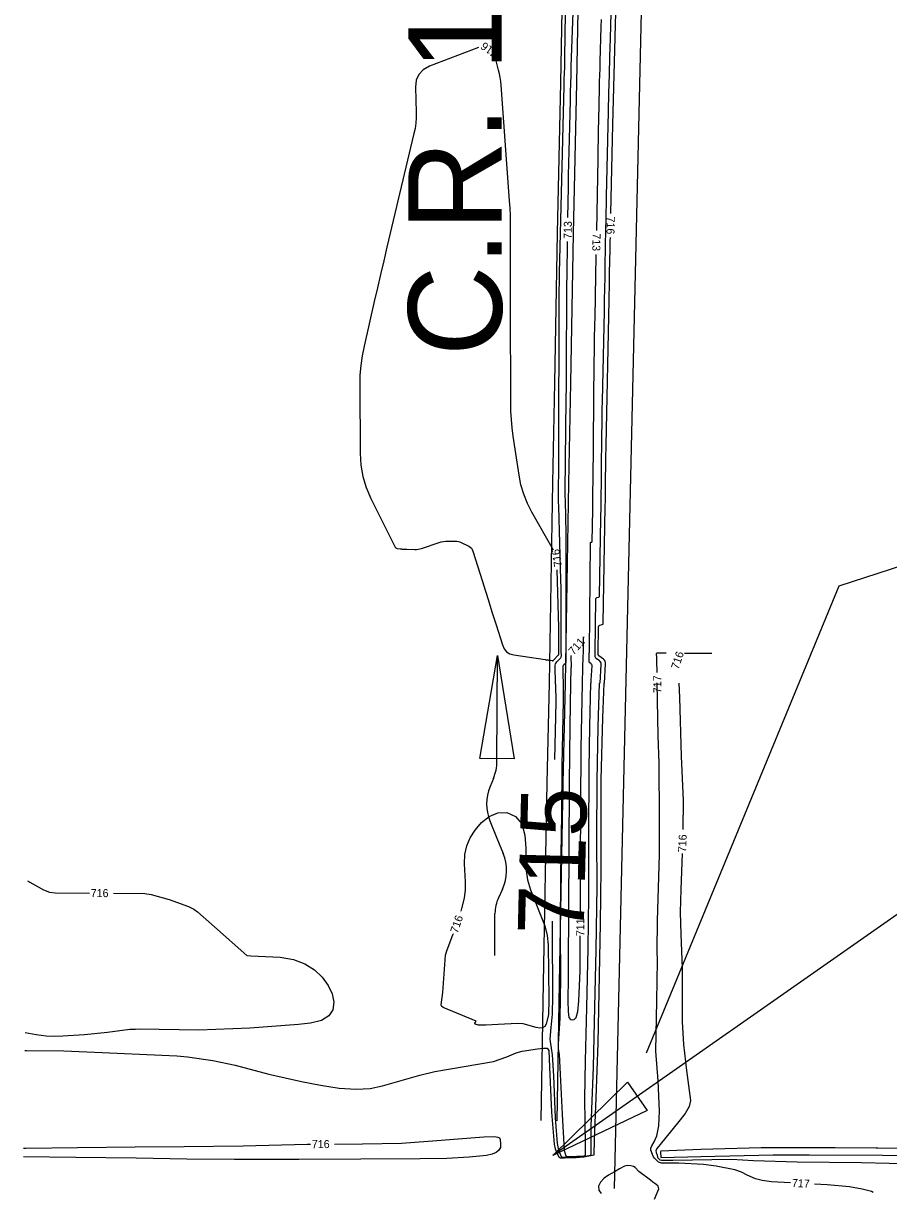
# Model space of a CAD drawing. Extents: x -468563856 to 36492962, y -306094093 to 11899197.
# Drawn here: x 1818863 to 1819296, y 531006 to 531590 of the extents above; entities that cross this region are included whole.
import ezdxf

# ---------------------------------------------------------------- set-up
doc = ezdxf.new("R2010")
doc.units = 0
for name, color, linetype in [('DT_X_Contour_Minor', 7, 'Continuous'), ('DT_X_Terrain_Boundary', 7, 'Continuous'), ('Level 19', 7, 'Continuous'), ('Level 31', 7, 'Continuous'), ('Level 40', 7, 'Continuous'), ('Level 56', 7, 'Continuous')]:
    doc.layers.add(name, color=color, linetype=linetype)

msp = doc.modelspace()

# ---------------------------------------------------------------- linework, layer by layer
at = {"layer": 'DT_X_Contour_Minor'}
for points in [[(1819157.17, 531495.03), (1819158.17, 531539.46), (1819158.46, 531551.92), (1819158.77, 531564.38), (1819159.09, 531576.84), (1819159.44, 531589.3), (1819161.01, 531644.73), (1819161.09, 531647.34), (1819161.18, 531649.96), (1819161.27, 531652.58), (1819161.37, 531655.2), (1819161.72, 531663.74), (1819161.79, 531665.58), (1819161.86, 531667.41), (1819161.92, 531669.24), (1819161.98, 531671.07), (1819164.36, 531744.92)], [(1819129.49, 531260), (1819129.26, 531268.51), (1819129.3, 531269.17), (1819129.47, 531269.79), (1819129.76, 531270.35), (1819130.17, 531270.87), (1819131.96, 531272.75), (1819132.14, 531272.98), (1819132.27, 531273.22), (1819132.34, 531273.49), (1819132.37, 531273.78), (1819132.37, 531274.75), (1819132.36, 531274.96), (1819132.36, 531275.17), (1819132.36, 531275.37), (1819132.36, 531275.58), (1819132.34, 531295.09), (1819132.32, 531299.27), (1819132.28, 531303.45), (1819132.2, 531307.63), (1819132.1, 531311.81), (1819131.05, 531348.48), (1819130.99, 531350.89), (1819130.96, 531353.3), (1819130.95, 531355.71), (1819130.96, 531358.12), (1819131.04, 531365.99), (1819131.06, 531367.67), (1819131.07, 531369.36), (1819131.08, 531371.04), (1819131.09, 531372.73), (1819131.34, 531454.17), (1819131.34, 531455.91), (1819131.36, 531457.64), (1819131.38, 531459.37), (1819131.4, 531461.1), (1819131.49, 531466.76), (1819131.51, 531467.98), (1819131.54, 531469.19), (1819131.56, 531470.4), (1819131.59, 531471.62), (1819133.73, 531558.76), (1819133.77, 531560.17), (1819133.81, 531561.58), (1819133.85, 531562.99), (1819133.89, 531564.4), (1819134.04, 531569), (1819134.07, 531569.99), (1819134.1, 531570.97), (1819134.12, 531571.96), (1819134.14, 531572.95), (1819134.86, 531617.56)], [(1819151.72, 531260.14), (1819152.25, 531269.51), (1819152.22, 531270.06), (1819152.07, 531270.54), (1819151.79, 531270.97), (1819151.4, 531271.34), (1819149.83, 531272.53), (1819149.59, 531272.76), (1819149.42, 531273.01), (1819149.33, 531273.3), (1819149.31, 531273.62), (1819149.34, 531274.73), (1819149.35, 531274.97), (1819149.35, 531275.21), (1819149.36, 531275.44), (1819149.36, 531275.68), (1819149.63, 531302.24), (1819149.67, 531302.51), (1819149.77, 531302.72), (1819149.95, 531302.88), (1819150.19, 531302.99), (1819151.1, 531303.26), (1819151.27, 531303.33), (1819151.39, 531303.44), (1819151.47, 531303.59), (1819151.49, 531303.78), (1819152.17, 531342.63), (1819152.27, 531348.44), (1819152.35, 531354.26), (1819152.43, 531360.08), (1819152.49, 531365.9), (1819152.69, 531384.9), (1819152.74, 531388.97), (1819152.79, 531393.05), (1819152.86, 531397.12), (1819152.94, 531401.19), (1819153.88, 531446.12), (1819154, 531451.81), (1819154.11, 531457.51), (1819154.22, 531463.2), (1819154.32, 531468.89), (1819154.67, 531487.49), (1819154.74, 531491.47), (1819154.82, 531495.46), (1819154.9, 531499.44), (1819154.99, 531503.43), (1819155.95, 531546.05), (1819156.16, 531555.19), (1819156.38, 531564.32), (1819156.62, 531573.45), (1819156.88, 531582.58), (1819157.97, 531621.19)], [(1819135.67, 531492.95), (1819135.92, 531508.2), (1819136.02, 531514.18), (1819136.13, 531520.16), (1819136.26, 531526.15), (1819136.4, 531532.13), (1819136.88, 531551.68), (1819136.99, 531555.86), (1819137.1, 531560.05), (1819137.23, 531564.24), (1819137.36, 531568.43), (1819138.54, 531604.73)], [(1819150.06, 531486.44), (1819150.72, 531522.35), (1819150.81, 531527.18), (1819150.9, 531532.01), (1819151, 531536.84), (1819151.11, 531541.67), (1819151.46, 531557.44), (1819151.54, 531560.82), (1819151.62, 531564.2), (1819151.71, 531567.58), (1819151.81, 531570.96), (1819152.3, 531588.34), (1819152.41, 531592.07)], [(1819090.94, 531578.05), (1819066.45, 531568.59), (1819063.32, 531566.89), (1819061.11, 531564.58), (1819059.82, 531561.66), (1819059.46, 531558.13), (1819059.75, 531545.57), (1819059.73, 531542.89), (1819059.54, 531540.23), (1819059.17, 531537.58), (1819058.64, 531534.96), (1819045.12, 531478.22), (1819043.51, 531471.41), (1819041.91, 531464.59), (1819040.33, 531457.77), (1819038.76, 531450.95), (1819033.66, 531428.65), (1819032.71, 531423.86), (1819032.03, 531419.04), (1819031.63, 531414.18), (1819031.51, 531409.3)], [(1819128.46, 531326.75), (1819117.68, 531345.6), (1819115.4, 531350.03), (1819113.56, 531354.62), (1819112.17, 531359.37), (1819111.21, 531364.26), (1819108.34, 531383.65), (1819107.8, 531387.81), (1819107.41, 531391.98), (1819107.16, 531396.16), (1819107.07, 531400.35), (1819106.87, 531448.67), (1819106.85, 531453.9), (1819106.85, 531459.13), (1819106.86, 531464.36), (1819106.88, 531469.59), (1819106.97, 531486.68), (1819106.95, 531490.35), (1819106.86, 531494), (1819106.7, 531497.66), (1819106.47, 531501.32), (1819102.27, 531559.1), (1819102.08, 531561.03), (1819101.8, 531562.94), (1819101.43, 531564.83), (1819100.96, 531566.71), (1819099.53, 531571.93)], [(1819153.97, 531260.16), (1819154.51, 531269.84), (1819154.47, 531270.52), (1819154.28, 531271.12), (1819153.95, 531271.66), (1819153.46, 531272.12), (1819151.08, 531273.92), (1819150.96, 531274.03), (1819150.88, 531274.16), (1819150.83, 531274.3), (1819150.82, 531274.46), (1819150.84, 531275.01), (1819150.84, 531275.13), (1819150.85, 531275.25), (1819150.85, 531275.36), (1819150.85, 531275.48), (1819150.98, 531288.21), (1819151.03, 531288.55), (1819151.16, 531288.82), (1819151.38, 531289.02), (1819151.69, 531289.16), (1819152.85, 531289.51), (1819153.07, 531289.6), (1819153.23, 531289.75), (1819153.32, 531289.94), (1819153.36, 531290.17), (1819154.37, 531348.5), (1819154.42, 531351.53), (1819154.47, 531354.56), (1819154.51, 531357.59), (1819154.54, 531360.62), (1819154.64, 531370.52), (1819154.67, 531372.65), (1819154.7, 531374.77), (1819154.73, 531376.89), (1819154.78, 531379.01), (1819156.29, 531451.72), (1819156.35, 531454.66), (1819156.41, 531457.6), (1819156.47, 531460.53), (1819156.52, 531463.47), (1819156.7, 531473.07), (1819156.74, 531475.13), (1819156.78, 531477.18), (1819156.82, 531479.24), (1819156.87, 531481.3), (1819156.9, 531483.03)], [(1819133.4, 531260.03), (1819133.4, 531260.31), (1819133.39, 531261.6), (1819133.36, 531262.9), (1819133.22, 531268.25), (1819133.24, 531268.58), (1819133.32, 531268.89), (1819133.47, 531269.18), (1819133.68, 531269.44), (1819134.45, 531270.25), (1819134.6, 531270.43), (1819134.7, 531270.63), (1819134.76, 531270.85), (1819134.78, 531271.08), (1819134.77, 531273.94), (1819134.77, 531274.55), (1819134.77, 531275.16), (1819134.77, 531275.78), (1819134.77, 531276.39), (1819134.71, 531336.26), (1819134.7, 531338.24), (1819134.67, 531340.21), (1819134.64, 531342.19), (1819134.59, 531344.16), (1819134.4, 531350.61), (1819134.37, 531352), (1819134.35, 531353.38), (1819134.35, 531354.76), (1819134.35, 531356.14), (1819134.82, 531402.33), (1819134.88, 531408.43), (1819134.93, 531414.53), (1819134.96, 531420.63), (1819134.98, 531426.73), (1819135.05, 531446.66), (1819135.07, 531450.93), (1819135.1, 531455.2), (1819135.15, 531459.47), (1819135.21, 531463.74), (1819135.48, 531480.95)], [(1819147.24, 531260.11), (1819147.24, 531260.21), (1819147.33, 531261.83), (1819147.72, 531268.86), (1819147.71, 531269.13), (1819147.63, 531269.37), (1819147.49, 531269.59), (1819147.29, 531269.78), (1819146.55, 531270.34), (1819146.41, 531270.47), (1819146.31, 531270.62), (1819146.26, 531270.79), (1819146.24, 531270.99), (1819146.33, 531273.88), (1819146.35, 531274.5), (1819146.37, 531275.12), (1819146.38, 531275.75), (1819146.38, 531276.37), (1819146.93, 531330.3), (1819146.95, 531330.42), (1819146.99, 531330.52), (1819147.07, 531330.59), (1819147.18, 531330.64), (1819147.59, 531330.76), (1819147.66, 531330.79), (1819147.72, 531330.84), (1819147.75, 531330.91), (1819147.77, 531330.99), (1819148.04, 531346.86), (1819148.1, 531350.26), (1819148.15, 531353.66), (1819148.19, 531357.06), (1819148.23, 531360.46), (1819148.86, 531421.28), (1819148.91, 531425.44), (1819148.96, 531429.6), (1819149.03, 531433.76), (1819149.12, 531437.92), (1819149.4, 531451.51), (1819149.46, 531454.42), (1819149.52, 531457.33), (1819149.57, 531460.24), (1819149.63, 531463.16), (1819149.84, 531474.45)], [(1819031.51, 531409.3), (1819031.65, 531375.1), (1819032, 531369.22), (1819033.01, 531363.5), (1819034.68, 531357.93), (1819037.01, 531352.52), (1819049, 531328.46), (1819049.23, 531328.1), (1819049.53, 531327.82), (1819049.89, 531327.63), (1819050.31, 531327.53), (1819051.79, 531327.35), (1819052.11, 531327.31), (1819052.43, 531327.28), (1819052.75, 531327.26), (1819053.07, 531327.24), (1819054.12, 531327.2), (1819054.34, 531327.19), (1819054.57, 531327.19), (1819054.8, 531327.18), (1819055.02, 531327.17), (1819059.08, 531327.01), (1819059.94, 531327.02), (1819060.79, 531327.11), (1819061.63, 531327.27), (1819062.46, 531327.51), (1819071.24, 531330.52), (1819072.32, 531330.85), (1819073.41, 531331.07), (1819074.51, 531331.21), (1819075.63, 531331.26), (1819079.32, 531331.26), (1819080.1, 531331.21), (1819080.85, 531331.08), (1819081.59, 531330.86), (1819082.31, 531330.55), (1819086.03, 531328.71), (1819086.76, 531328.26), (1819087.35, 531327.69), (1819087.82, 531327.01), (1819088.15, 531326.22), (1819092.89, 531311.08), (1819093.56, 531308.92), (1819094.24, 531306.76), (1819094.92, 531304.6), (1819095.59, 531302.44), (1819097.8, 531295.38), (1819098.27, 531293.86), (1819098.75, 531292.35), (1819099.22, 531290.84), (1819099.7, 531289.33), (1819102.85, 531279.31), (1819103.72, 531277.39), (1819104.98, 531275.93), (1819106.62, 531274.91), (1819108.65, 531274.35), (1819124.27, 531271.99), (1819124.69, 531271.93), (1819125.11, 531271.86), (1819125.53, 531271.8), (1819125.94, 531271.74), (1819127.8, 531271.46), (1819127.85, 531271.45), (1819127.9, 531271.44), (1819127.95, 531271.43), (1819128, 531271.43), (1819128.16, 531271.4), (1819128.19, 531271.4), (1819128.22, 531271.41), (1819128.25, 531271.42), (1819128.27, 531271.44), (1819131.02, 531274.32), (1819131.08, 531274.4), (1819131.13, 531274.49), (1819131.15, 531274.58), (1819131.16, 531274.68), (1819131.16, 531275.02), (1819131.16, 531275.09), (1819131.16, 531275.17), (1819131.16, 531275.24), (1819131.16, 531275.31), (1819131.15, 531282.14), (1819131.15, 531283.61), (1819131.13, 531285.07), (1819131.1, 531286.53), (1819131.07, 531287.99), (1819130.25, 531316.77)], [(1819143.01, 531260.09), (1819143.18, 531268), (1819143.19, 531268.02), (1819143.19, 531268.05), (1819143.19, 531268.07), (1819143.19, 531268.09), (1819143.19, 531268.2), (1819143.19, 531268.2), (1819143.19, 531268.21), (1819143.19, 531268.21), (1819143.19, 531268.21), (1819143.18, 531268.22), (1819143.18, 531268.22), (1819143.17, 531268.22), (1819143.17, 531268.23), (1819143.17, 531268.23), (1819143.32, 531273), (1819143.35, 531274.02), (1819143.38, 531275.04), (1819143.4, 531276.07), (1819143.41, 531277.09), (1819143.46, 531282.43), (1819143.46, 531283.15), (1819143.44, 531283.39), (1819143.4, 531283.15), (1819143.34, 531282.43), (1819143.23, 531280.88)], [(1819137.18, 531274.02), (1819137.2, 531268.03), (1819137.2, 531268.02), (1819137.2, 531268.02), (1819137.2, 531268.02), (1819137.19, 531268.01), (1819137.18, 531268), (1819137.18, 531268), (1819137.18, 531268), (1819137.18, 531267.99), (1819137.18, 531267.99), (1819137.18, 531267.91), (1819137.18, 531267.89), (1819137.18, 531267.88), (1819137.18, 531267.86), (1819137.18, 531267.84), (1819137.03, 531260.05)], [(1819180.29, 531265.54), (1819180.18, 531271.36), (1819180.17, 531271.82), (1819180.15, 531272.27), (1819180.12, 531272.73), (1819180.09, 531273.19), (1819179.96, 531274.68), (1819179.98, 531274.96), (1819180.08, 531275.15), (1819180.28, 531275.27), (1819180.55, 531275.31), (1819182.71, 531275.31), (1819182.95, 531275.31), (1819183.19, 531275.31), (1819183.43, 531275.31), (1819183.67, 531275.32), (1819184.8, 531275.33)], [(1819194.06, 531275.15), (1819206.72, 531275.14), (1819206.82, 531275.14), (1819206.93, 531275.14), (1819207.03, 531275.14), (1819207.14, 531275.14), (1819207.62, 531275.14)], [(1819246.98, 531010.39), (1819237.57, 531010.89), (1819232.84, 531011.48), (1819229.42, 531012.31), (1819225.31, 531014.23), (1819222.55, 531015.72), (1819219.15, 531016.84), (1819209.9, 531018.76), (1819203.53, 531019.55), (1819190.9, 531020.16), (1819182.53, 531020.26), (1819181.01, 531020.74), (1819178.9, 531022.64), (1819178.48, 531023.41), (1819178.02, 531024.48), (1819177.06, 531026.68), (1819177.08, 531027.63), (1819177.61, 531028.92), (1819178.77, 531030.81), (1819180.14, 531033.91), (1819181.18, 531038.93), (1819181.5, 531046.17), (1819180.82, 531061.38), (1819179.63, 531076.19), (1819180.11, 531101.3), (1819180.42, 531121.42), (1819180.29, 531126.46), (1819180.49, 531141.28), (1819181.4, 531174.31), (1819181.48, 531192.4), (1819181.23, 531220.22), (1819180.87, 531233.86), (1819180.35, 531260.37)], [(1818864.04, 531076.5), (1818864.77, 531076.52), (1818883.56, 531076.41), (1818902.71, 531075.57), (1818932.49, 531074.12), (1818940.08, 531073.83), (1818945.34, 531073.38), (1818957.99, 531071.57), (1818969.24, 531069.19), (1818986.01, 531064.73), (1819002.41, 531061), (1819011.8, 531059.17), (1819021.18, 531057.74), (1819029.7, 531057.11), (1819036.78, 531057.53), (1819042.87, 531058.78), (1819061.52, 531064.23), (1819069.08, 531065.94), (1819098.47, 531071.1), (1819105.08, 531073.39), (1819109.81, 531075.37), (1819112.74, 531076.19), (1819120.36, 531077.41), (1819123.52, 531077.71), (1819125.32, 531077.63), (1819126.06, 531076.49), (1819126.52, 531068.18), (1819127.45, 531045.77), (1819128.79, 531029.62), (1819129.34, 531027.38), (1819130.44, 531024.55), (1819131.15, 531023.37), (1819131.9, 531022.82), (1819133.12, 531022.86), (1819133.91, 531022.93), (1819139.86, 531023.05), (1819143.63, 531023.3), (1819148.72, 531024.32), (1819149, 531031.83), (1819149.86, 531052.92), (1819150.71, 531080.12), (1819151.44, 531114.19), (1819151.99, 531139.95), (1819152.3, 531167.43), (1819152.23, 531194.82), (1819152.34, 531211.83), (1819153.08, 531242.86), (1819153.71, 531260.16)], [(1819127.77, 531141.24), (1819127.8, 531135.83), (1819128, 531103.67), (1819127.83, 531094.71), (1819127.12, 531087.94), (1819126.53, 531082.22), (1819127.2, 531077.65), (1819127.71, 531074.35), (1819128.37, 531063.92), (1819129.33, 531042.8), (1819130.36, 531030.07), (1819130.99, 531026.66), (1819132.33, 531023.57), (1819133.05, 531023.25), (1819133.87, 531023.27), (1819135.48, 531023.14), (1819143.35, 531023.45), (1819147.09, 531024.16), (1819147.29, 531024.66), (1819147.37, 531038.73), (1819148.39, 531068.13), (1819149.11, 531098.2), (1819149.76, 531126.8), (1819150.22, 531158.63), (1819150.2, 531182.74), (1819150.29, 531211.47), (1819150.86, 531238.39), (1819151.49, 531260.14)], [(1819129.26, 531260), (1819129.37, 531259.5), (1819129.6, 531250.63), (1819129, 531222)], [(1819133.25, 531260.03), (1819133.22, 531251.32), (1819132.61, 531219.05), (1819132.38, 531194.32), (1819131.95, 531164.44), (1819131.75, 531137.2), (1819131.89, 531112.6), (1819131.53, 531092.68), (1819130.78, 531079.87), (1819130.8, 531077.32), (1819131.28, 531074.5), (1819131.67, 531067.99), (1819132.7, 531044.74), (1819133.83, 531026.46), (1819134.6, 531023.89), (1819135, 531023.69), (1819136.37, 531023.53), (1819143.74, 531023.92), (1819144.44, 531024.23), (1819144.43, 531029.2), (1819144.09, 531052.52), (1819144.5, 531071.41), (1819145.15, 531097.96), (1819145.84, 531127.7), (1819146.06, 531153.64), (1819146.1, 531183.59), (1819146.26, 531217.29), (1819146.68, 531238.54), (1819147.13, 531260.11)], [(1819136.98, 531260.05), (1819136.59, 531238.81), (1819136.2, 531210.08), (1819136.11, 531176.15), (1819136, 531148.71), (1819135.85, 531117.51), (1819135.75, 531113.03), (1819135.59, 531101.41), (1819135.74, 531096.08), (1819136.19, 531093.09), (1819136.89, 531091.98), (1819137.79, 531091.82), (1819138.79, 531091.98), (1819139.78, 531093.08), (1819140.6, 531096.06), (1819141.15, 531101.39), (1819141.71, 531116.34), (1819141.82, 531133.82)], [(1819141.88, 531145.82), (1819141.99, 531169.8), (1819142.06, 531199.34), (1819142.28, 531227.46), (1819142.91, 531260.09)], [(1819191.08, 531260.22), (1819191.52, 531252.94), (1819192.32, 531223.61), (1819193.27, 531201.57), (1819193.15, 531186.99)], [(1819082.17, 531146.25), (1819082.62, 531147.58), (1819083.87, 531152.63), (1819084.41, 531156.79), (1819084.45, 531160.79), (1819083.96, 531169.86), (1819084.16, 531174.47), (1819085.09, 531178.79), (1819086.8, 531182.85), (1819089.26, 531186.76), (1819092.45, 531190.49), (1819096.26, 531193.57), (1819100.57, 531195.39), (1819105.15, 531195.44), (1819109.39, 531193.59), (1819112.55, 531189.78), (1819114.14, 531184.17), (1819114.6, 531177.7), (1819114.78, 531166.38), (1819115.46, 531161.79), (1819116.91, 531156.85), (1819124.08, 531138.9), (1819125.32, 531134.05), (1819125.8, 531129.35), (1819126.08, 531102.05), (1819125.91, 531094.57), (1819124.8, 531089.72), (1819124.08, 531088.53), (1819122.99, 531087.85), (1819121.57, 531087.67), (1819119.84, 531087.94), (1819113.23, 531089.81), (1819110.66, 531090), (1819103.85, 531089.62), (1819094.55, 531089.11), (1819091, 531089.18), (1819089.33, 531089.61), (1819089.05, 531090.22), (1819089.68, 531091.23), (1819073.29, 531097.99), (1819072.47, 531098.72), (1819072.24, 531099.38), (1819073.04, 531105.52), (1819074.47, 531124.24), (1819075.12, 531126.43), (1819078.33, 531134.81), (1819078.35, 531134.88)], [(1819192.75, 531175), (1819192.1, 531156.98), (1819191.85, 531145.72), (1819192.13, 531134.62), (1819192.87, 531117.7), (1819192.85, 531101.16), (1819192.86, 531090.86), (1819193.47, 531079.47), (1819194.94, 531066.59), (1819196.91, 531051.54), (1819196.34, 531048.59), (1819194.3, 531045.07), (1819190.53, 531040.2), (1819180.28, 531027.7), (1819179.62, 531026.48), (1819179.84, 531025.6), (1819180.23, 531024.22), (1819180.48, 531022.97), (1819181.56, 531021.9), (1819182.49, 531021.66), (1819188.19, 531021.69), (1819217.44, 531022.11), (1819228.52, 531021.48), (1819250.34, 531020.87), (1819282.61, 531020.48), (1819310.2, 531019.87)], [(1818865.34, 531161.35), (1818873.3, 531156.93), (1818876.33, 531155.74), (1818879.15, 531155.31), (1818896.27, 531155.24)], [(1818908.27, 531155.17), (1818923.93, 531155), (1818927.12, 531154.51), (1818936.15, 531151.98), (1818945.78, 531148.57), (1818948.48, 531147.23), (1818950.29, 531145.88), (1818958.87, 531138.41), (1818975.11, 531124.05), (1818976.99, 531123.82), (1818991.76, 531123.19), (1818998.37, 531122.05), (1819004.1, 531119.91), (1819008.85, 531116.9), (1819012.68, 531113.22), (1819015.66, 531109.09), (1819017.66, 531104.8), (1819018.52, 531100.64), (1819018.06, 531096.9), (1819016.09, 531093.79), (1819012.37, 531091.5), (1819006.95, 531090.14), (1819000.83, 531089.46), (1818976.56, 531087.69), (1818950.95, 531086.65), (1818921.27, 531087.26), (1818919.37, 531087.09), (1818916.43, 531086.97), (1818905.25, 531085.55), (1818893.8, 531084.36), (1818882.92, 531083.64), (1818878.76, 531083.52), (1818874.7, 531083.7), (1818869.62, 531084.34), (1818864.18, 531085.33)], [(1819018.88, 531029.77), (1819032.86, 531029.88), (1819052.46, 531030.24), (1819065.68, 531031.18), (1819093.59, 531033.42), (1819098.99, 531033.45), (1819100.55, 531033.23), (1819101.37, 531032.78), (1819101.74, 531032.01), (1819101.92, 531029.78), (1819101.88, 531028.08), (1819100.86, 531026.58), (1819099.72, 531025.57), (1819097.78, 531024.64), (1819094.85, 531024), (1819086.32, 531023.23), (1819075, 531022.58), (1819061.69, 531022.29), (1819032.02, 531022.15), (1819001.02, 531022), (1818968.8, 531022.01), (1818945.01, 531022.2), (1818919.71, 531022.64), (1818889.52, 531022.94), (1818863.23, 531023.41)], [(1818863.29, 531027.72), (1818864.39, 531027.76), (1818890.26, 531028.09), (1818919.18, 531028.42), (1818943.71, 531028.59), (1818973.23, 531028.9), (1819005.23, 531029.65), (1819006.89, 531029.67)], [(1819290.71, 531027.75), (1819289.76, 531027.7), (1819269.41, 531027.78), (1819232.31, 531027.81), (1819202.07, 531026.99), (1819182.06, 531026.15), (1819182, 531025.8), (1819182.11, 531023.05), (1819202.07, 531023.57), (1819238.31, 531024.4), (1819256.31, 531024.34), (1819293.11, 531024.2), (1819312.02, 531024.06)], [(1819325.48, 531027.5), (1819290.71, 531027.75)], [(1819179.04, 531002.13), (1819181.2, 531007.31), (1819180.76, 531008.64), (1819179.58, 531009.74), (1819178.14, 531010.7), (1819177.04, 531011.7), (1819171.11, 531016.1), (1819169.37, 531018.05), (1819168.46, 531018.56), (1819167.15, 531018.88), (1819165.59, 531018.96), (1819164.02, 531018.72), (1819161.4, 531017.38), (1819159.24, 531016.06), (1819159.02, 531015.93), (1819155.91, 531014.15), (1819153.85, 531012.62), (1819151.97, 531010.74), (1819150.93, 531008.72), (1819151.2, 531006.75), (1819152.34, 531004.97)], [(1819288.3, 531005.54), (1819287.5, 531006.1), (1819282.85, 531007.27), (1819276.55, 531008.42), (1819265.4, 531009.4), (1819258.97, 531009.75)]]:
    msp.add_lwpolyline(points, dxfattribs=at)
at = {"layer": 'DT_X_Terrain_Boundary'}
msp.add_line((1819179.82, 531921.31), (1819158.8, 531007.53), dxfattribs=at)
at = {"layer": 'Level 31'}
for p, q in [((1819091.56, 531222.5), (1819100.44, 531274.03)), ((1819100.15, 531221.08), (1819100.44, 531274.03)), ((1819100.44, 531274.03), (1819108.73, 531222.41)), ((1819108.73, 531222.41), (1819091.56, 531222.5)), ((1819098.43, 531212.54), (1819096.71, 531208.45)), ((1819096.61, 531191.35), (1819100.11, 531182.71)), ((1819100.11, 531182.71), (1819103.27, 531175.04)), ((1819102.87, 531157.12), (1819100.92, 531152.9)), ((1819099.04, 531124.04), (1819099.15, 531144.96))]:
    msp.add_line(p, q, dxfattribs=at)
for centre, radius, start, end in [((1819077.76, 531221.2), 22.4, 337.3227, 359.68272), ((1819117.37, 531199.79), 22.4, 157.28387, 202.12773), ((1819082.54, 531166.55), 22.4, 335.15003, 22.25849), ((1819118.35, 531144.87), 19.2, 155.19991, 179.68272)]:
    msp.add_arc(centre, radius, start, end, dxfattribs=at)
at = {"layer": 'Level 40'}
for p, q in [((1819305.32, 531147.99), (1819128.03, 531024.1)), ((1819128.03, 531024.1), (1819165.4, 531060.67)), ((1819165.4, 531060.67), (1819175.23, 531046.59)), ((1819175.23, 531046.59), (1819128.03, 531024.1))]:
    msp.add_line(p, q, dxfattribs=at)
msp.add_lwpolyline([(1819175.03, 531075.3), (1819271.41, 531308.82), (1820002.43, 531546.16)], dxfattribs=at)
at = {"layer": 'Level 56'}
for points in [[(1819122.25, 531041.53), (1819123.49, 531110.37), (1819125.23, 531210.36), (1819126.4, 531260.35), (1819128.19, 531360.33), (1819129.12, 531410.32), (1819130.49, 531485.11), (1819132.06, 531560.29), (1819134.01, 531660.27), (1819136.23, 531760.25), (1819137.31, 531810.24), (1819139.44, 531910.21), (1819140.49, 531960.2)], [(1819130.25, 531041.36), (1819131.48, 531110.21), (1819133.23, 531210.2), (1819134.4, 531260.18), (1819136.18, 531360.17), (1819137.12, 531410.16), (1819138.49, 531484.95), (1819140.06, 531560.13), (1819142, 531660.11), (1819144.22, 531760.09), (1819145.31, 531810.08), (1819147.43, 531910.05), (1819148.49, 531960.04)]]:
    msp.add_lwpolyline(points, dxfattribs=at)

# ---------------------------------------------------------------- texts
at = {"layer": 'Level 19'}
for s, height, rotation, p in [('716', 4, 144.49224, (1819101.2, 531575.81)), ('713', 4, 89.08781, (1819137.5, 531482.24)), ('716', 4, 268.71563, (1819155.14, 531493.55)), ('713', 4, 268.94721, (1819148.03, 531485.16)), ('716', 4, 100.13194, (1819132.83, 531318.71)), ('711', 4, 48.57548, (1819138.53, 531273.99)), ('716', 4, 71.75602, (1819190.95, 531266.8)), ('717', 4, 91.05326, (1819182.48, 531255.2)), ('715', 33, 88.61938, (1819143.52, 531134.06)), ('716', 4, 87.93756, (1819194.77, 531175.57)), ('716', 4, 359.73155, (1818896.91, 531153.23)), ('716', 4, 71.44211, (1819080.46, 531134.85)), ('711', 4, 89.73092, (1819143.82, 531133.67)), ('716', 4, 0.48128, (1819007.55, 531027.67)), ('717', 4, 356.92979, (1819247.62, 531008.35))]:
    msp.add_text(s, height=height, rotation=rotation, dxfattribs=at).set_placement(p)
at = {"layer": 'Level 40'}
msp.add_text('C.R. 123', height=46.8, rotation=90, dxfattribs=at).set_placement((1819102.58, 531423.72))

doc.saveas('drawing.dxf')
